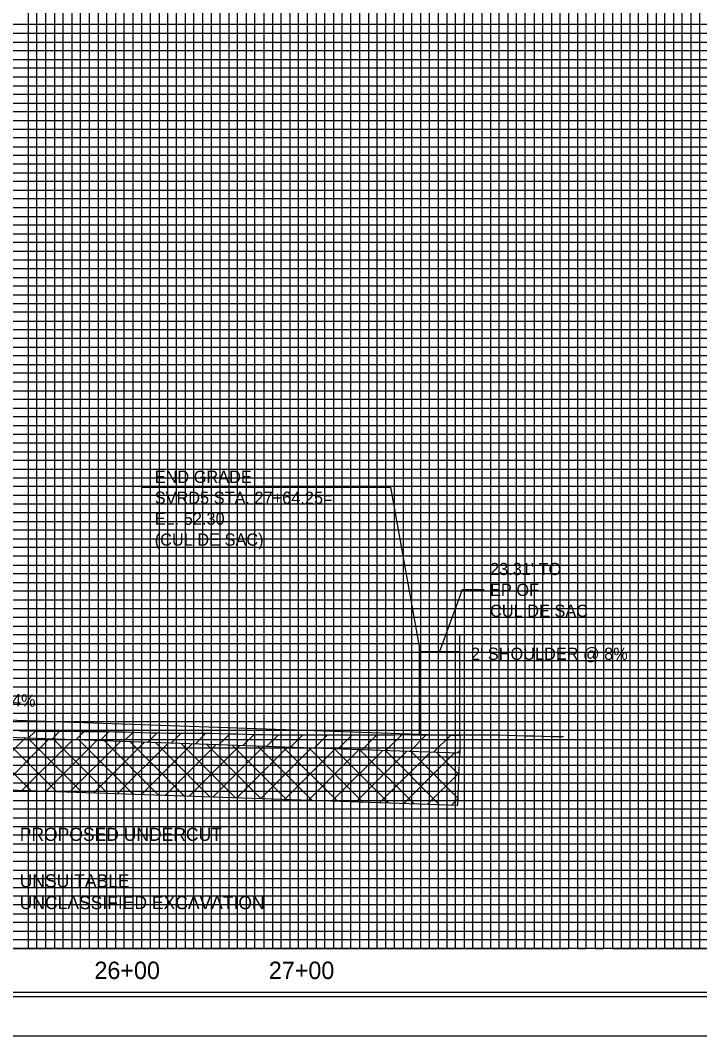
# Model space of a CAD drawing. Extents: x 2345490 to 2436403, y 465165 to 573888.
# Drawn here: x 2383276 to 2383665, y 491453 to 492035 of the extents above; entities that cross this region are included whole.
import ezdxf

# ---------------------------------------------------------------- set-up
doc = ezdxf.new("R2010")
doc.units = 0
for name, color, linetype in [('Default', 7, 'Continuous'), ('Old_Level_1', 7, 'Continuous'), ('Old_Level_18', 7, 'Continuous'), ('Old_Level_2', 7, 'Continuous'), ('Old_Level_41', 7, 'Continuous'), ('Old_Level_42', 7, 'Continuous'), ('Old_Level_43', 7, 'Continuous'), ('Old_Level_5', 7, 'Continuous'), ('Old_Level_50', 7, 'Continuous'), ('Old_Level_51', 7, 'Continuous'), ('Old_Level_62', 7, 'Continuous'), ('Old_Level_63', 7, 'Continuous'), ('Prop Vertical Profile Grade', 7, 'Continuous')]:
    doc.layers.add(name, color=color, linetype=linetype)

msp = doc.modelspace()

# ---------------------------------------------------------------- linework, layer by layer
at = {"layer": 'Default'}
msp.add_line((2383527.68499, 491625.10225), (2383527.68499, 491615.09754), dxfattribs=at)
at = {"layer": 'Old_Level_1'}
msp.add_lwpolyline([(2383275.125, 491627.81575), (2383280.125, 491627.77375), (2383285.125, 491627.7315), (2383290.125, 491627.6895), (2383295.125, 491627.6475), (2383300.125, 491627.60475), (2383305.125, 491627.56175), (2383310.125, 491627.5185), (2383315.125, 491627.4755), (2383320.125, 491627.43225), (2383325.125, 491627.389), (2383330.125, 491627.30725), (2383335.125, 491627.17775), (2383340.125, 491627.04825), (2383345.125, 491626.91875), (2383350.125, 491626.78925), (2383355.125, 491626.6595), (2383360.125, 491626.533), (2383365.125, 491626.53275), (2383370.125, 491626.5325), (2383375.125, 491626.53225), (2383380.125, 491626.532), (2383385.125, 491626.4805), (2383390.125, 491626.347), (2383395.125, 491626.2135), (2383400.125, 491626.08), (2383405.125, 491625.9465), (2383410.125, 491625.813), (2383415.125, 491625.6795), (2383420.125, 491625.546), (2383425.125, 491625.506), (2383430.125, 491625.5225), (2383435.125, 491625.53875), (2383440.125, 491625.5515), (2383445.125, 491625.5565), (2383450.125, 491625.5615), (2383455.125, 491625.5665), (2383460.125, 491625.57125), (2383465.125, 491625.57625), (2383470.125, 491625.58125), (2383475.125, 491625.58625), (2383480.125, 491625.591), (2383485.125, 491625.602), (2383490.125, 491625.63275), (2383495.125, 491625.6515), (2383500.125, 491625.63575), (2383505.125, 491625.62025), (2383510.125, 491625.60475), (2383515.125, 491625.589), (2383520.125, 491625.5735), (2383525.125, 491625.55775), (2383530.125, 491625.54225), (2383535.125, 491625.5265), (2383540.125, 491625.511), (2383545.125, 491625.49525), (2383550.125, 491625.48975), (2383555.125, 491625.34), (2383560.125, 491625.19025), (2383565.125, 491625.04025), (2383570.125, 491624.8905), (2383575.125, 491624.7405), (2383580.125, 491624.66775), (2383585.125, 491624.6015), (2383587.125, 491624.575)], dxfattribs=at)
at = {"layer": 'Old_Level_18'}
msp.add_lwpolyline([(2384590.125, 492527.95225), (2383090.125, 492527.95225), (2383090.125, 491477.95225), (2384590.125, 491477.95225)], close=True, dxfattribs=at)
at = {"layer": 'Old_Level_2'}
for p, q in [((2383344.85425, 491767.688), (2383488.04875, 491767.688)), ((2383504.375, 491676.31075), (2383488.04875, 491767.688)), ((2383528.99175, 491708.7615), (2383515.985, 491673.4475)), ((2383541.55675, 491708.7615), (2383528.99175, 491708.7615)), ((2383527.685, 491625.237), (2383527.685, 491682.5075)), ((2383504.375, 491625.95225), (2383504.375, 491676.31075)), ((2383504.375, 491673.4475), (2383527.685, 491673.4475)), ((2383504.375, 491625.95225), (2383527.685, 491625.237))]:
    msp.add_line(p, q, dxfattribs=at)
at = {"layer": 'Old_Level_41'}
msp.add_line((2384590.125, 491502.95225), (2383090.125, 491502.95225), dxfattribs=at)
for points in [[(2383090.125, 492527.95225), (2383140.125, 492527.95225), (2383140.125, 491502.95225), (2383190.125, 491502.95225), (2383190.125, 492527.95225), (2383240.125, 492527.95225), (2383240.125, 491502.95225), (2383290.125, 491502.95225), (2383290.125, 492527.95225), (2383340.125, 492527.95225), (2383340.125, 491502.95225), (2383390.125, 491502.95225), (2383390.125, 492527.95225), (2383440.125, 492527.95225), (2383440.125, 491502.95225), (2383490.125, 491502.95225), (2383490.125, 492527.95225), (2383540.125, 492527.95225), (2383540.125, 491502.95225), (2383590.125, 491502.95225), (2383590.125, 492527.95225), (2383640.125, 492527.95225), (2383640.125, 491502.95225), (2383690.125, 491502.95225)], [(2383165.125, 491502.95225), (2383165.125, 492527.95225), (2383215.125, 492527.95225), (2383215.125, 491502.95225), (2383265.125, 491502.95225), (2383265.125, 492527.95225), (2383315.125, 492527.95225), (2383315.125, 491502.95225), (2383365.125, 491502.95225), (2383365.125, 492527.95225), (2383415.125, 492527.95225), (2383415.125, 491502.95225), (2383465.125, 491502.95225), (2383465.125, 492527.95225), (2383515.125, 492527.95225), (2383515.125, 491502.95225), (2383565.125, 491502.95225), (2383565.125, 492527.95225), (2383615.125, 492527.95225), (2383615.125, 491502.95225), (2383665.125, 491502.95225), (2383665.125, 492527.95225), (2383715.125, 492527.95225)], [(2384590.125, 492027.95225), (2383090.125, 492027.95225), (2383090.125, 491977.95225), (2384590.125, 491977.95225)], [(2384590.125, 491927.95225), (2383090.125, 491927.95225), (2383090.125, 491877.95225), (2384590.125, 491877.95225)], [(2384590.125, 491852.95225), (2383090.125, 491852.95225), (2383090.125, 491902.95225), (2384590.125, 491902.95225)], [(2384590.125, 491827.95225), (2383090.125, 491827.95225), (2383090.125, 491777.95225), (2384590.125, 491777.95225)], [(2384590.125, 491752.95225), (2383090.125, 491752.95225), (2383090.125, 491802.95225), (2384590.125, 491802.95225)], [(2384590.125, 491727.95225), (2383090.125, 491727.95225), (2383090.125, 491677.95225), (2384590.125, 491677.95225)], [(2384590.125, 491627.95225), (2383090.125, 491627.95225), (2383090.125, 491577.95225), (2384590.125, 491577.95225)], [(2384590.125, 491552.95225), (2383090.125, 491552.95225), (2383090.125, 491602.95225), (2384590.125, 491602.95225)], [(2384590.125, 491527.95225), (2383090.125, 491527.95225)]]:
    msp.add_lwpolyline(points, dxfattribs=at)
at = {"layer": 'Old_Level_42'}
for points in [[(2384590.125, 491952.95225), (2383090.125, 491952.95225), (2383090.125, 492002.95225), (2384590.125, 492002.95225)], [(2384590.125, 491652.95225), (2383090.125, 491652.95225), (2383090.125, 491702.95225), (2384590.125, 491702.95225)]]:
    msp.add_lwpolyline(points, dxfattribs=at)
at = {"layer": 'Old_Level_43'}
for points in [[(2383280.125, 492527.95225), (2383280.125, 491502.95225), (2383285.125, 491502.95225), (2383285.125, 492527.95225)], [(2383295.125, 492527.95225), (2383295.125, 491502.95225), (2383300.125, 491502.95225), (2383300.125, 492527.95225)], [(2383305.125, 491502.95225), (2383310.125, 491502.95225), (2383310.125, 492527.95225)], [(2383305.125, 492527.95225), (2383305.125, 491502.95225)], [(2383320.125, 492527.95225), (2383320.125, 491502.95225), (2383325.125, 491502.95225), (2383325.125, 492527.95225)], [(2383330.125, 492527.95225), (2383330.125, 491502.95225), (2383335.125, 491502.95225), (2383335.125, 492527.95225)], [(2383345.125, 492527.95225), (2383345.125, 491502.95225), (2383350.125, 491502.95225), (2383350.125, 492527.95225)], [(2383355.125, 492527.95225), (2383355.125, 491502.95225), (2383360.125, 491502.95225), (2383360.125, 492527.95225)], [(2383370.125, 492527.95225), (2383370.125, 491502.95225), (2383375.125, 491502.95225), (2383375.125, 492527.95225)], [(2383380.125, 492527.95225), (2383380.125, 491502.95225), (2383385.125, 491502.95225), (2383385.125, 492527.95225)], [(2383395.125, 492527.95225), (2383395.125, 491502.95225), (2383400.125, 491502.95225), (2383400.125, 492527.95225)], [(2383405.125, 492527.95225), (2383405.125, 491502.95225), (2383410.125, 491502.95225), (2383410.125, 492527.95225)], [(2383420.125, 492527.95225), (2383420.125, 491502.95225), (2383425.125, 491502.95225), (2383425.125, 492527.95225)], [(2383430.125, 492527.95225), (2383430.125, 491502.95225), (2383435.125, 491502.95225), (2383435.125, 492527.95225)], [(2383445.125, 492527.95225), (2383445.125, 491502.95225), (2383450.125, 491502.95225), (2383450.125, 492527.95225)], [(2383455.125, 492527.95225), (2383455.125, 491502.95225), (2383460.125, 491502.95225), (2383460.125, 492527.95225)], [(2383470.125, 492527.95225), (2383470.125, 491502.95225), (2383485.125, 491502.95225), (2383485.125, 492527.95225)], [(2383475.125, 492527.95225), (2383475.125, 491502.95225), (2383480.125, 491502.95225), (2383480.125, 492527.95225)], [(2383475.125, 492527.35225), (2383475.125, 491502.95225), (2383480.125, 491502.95225), (2383480.125, 492527.35225)], [(2383495.125, 492527.95225), (2383495.125, 491502.95225), (2383500.125, 491502.95225), (2383500.125, 492527.95225)], [(2383505.125, 492527.95225), (2383505.125, 491502.95225), (2383510.125, 491502.95225), (2383510.125, 492527.95225)], [(2383520.125, 492527.95225), (2383520.125, 491502.95225), (2383525.125, 491502.95225), (2383525.125, 492527.95225)], [(2383530.125, 492527.95225), (2383530.125, 491502.95225), (2383535.125, 491502.95225), (2383535.125, 492527.95225)], [(2383545.125, 492527.95225), (2383545.125, 491502.95225), (2383550.125, 491502.95225), (2383550.125, 492527.95225)], [(2383555.125, 492527.95225), (2383555.125, 491502.95225), (2383560.125, 491502.95225), (2383560.125, 492527.95225)], [(2383570.125, 492527.95225), (2383570.125, 491502.95225), (2383575.125, 491502.95225), (2383575.125, 492527.95225)], [(2383580.125, 492527.95225), (2383580.125, 491502.95225), (2383585.125, 491502.95225), (2383585.125, 492527.95225)], [(2383595.125, 492527.95225), (2383595.125, 491502.95225), (2383600.125, 491502.95225), (2383600.125, 492527.95225)], [(2383605.125, 492527.95225), (2383605.125, 491502.95225), (2383610.125, 491502.95225), (2383610.125, 492527.95225)], [(2383620.125, 492527.95225), (2383620.125, 491502.95225)], [(2383625.125, 492527.95225), (2383625.125, 491502.95225), (2383630.125, 491502.95225), (2383630.125, 492527.95225), (2383635.125, 492527.95225), (2383635.125, 491502.95225), (2383645.125, 491502.95225), (2383645.125, 492527.95225), (2383650.125, 492527.95225), (2383650.125, 491502.95225), (2383655.125, 491502.95225), (2383655.125, 492527.95225), (2383660.125, 492527.95225), (2383660.125, 491502.95225)], [(2384540.125, 492032.95225), (2383140.125, 492032.95225), (2383140.125, 492022.95225), (2384540.125, 492022.95225)], [(2384540.125, 492017.95225), (2383140.125, 492017.95225), (2383140.125, 492012.95225), (2384540.125, 492012.95225)], [(2384540.125, 492007.95225), (2383140.125, 492007.95225)], [(2383140.125, 491997.95225), (2384540.125, 491997.95225)], [(2384540.125, 491992.95225), (2383140.125, 491992.95225), (2383140.125, 491987.95225), (2384540.125, 491987.95225)], [(2384540.125, 491982.95225), (2383140.125, 491982.95225), (2383140.125, 491972.95225), (2384540.125, 491972.95225)], [(2384540.125, 491967.95225), (2383140.125, 491967.95225), (2383140.125, 491962.95225), (2384540.125, 491962.95225)], [(2384540.125, 491957.95225), (2383140.125, 491957.95225), (2383140.125, 491947.95225), (2384540.125, 491947.95225)], [(2384540.125, 491942.95225), (2383140.125, 491942.95225), (2383140.125, 491937.95225), (2384540.125, 491937.95225)], [(2384540.125, 491932.95225), (2383140.125, 491932.95225), (2383140.125, 491922.95225), (2384540.125, 491922.95225)], [(2384540.125, 491917.95225), (2383140.125, 491917.95225), (2383140.125, 491912.95225), (2384540.125, 491912.95225)], [(2384540.125, 491907.95225), (2383140.125, 491907.95225), (2383140.125, 491897.95225), (2384540.125, 491897.95225)], [(2384540.125, 491892.95225), (2383140.125, 491892.95225), (2383140.125, 491887.95225), (2384540.125, 491887.95225)], [(2384540.125, 491882.95225), (2383140.125, 491882.95225), (2383140.125, 491872.95225), (2384540.125, 491872.95225)], [(2384540.125, 491867.95225), (2383140.125, 491867.95225), (2383140.125, 491862.95225), (2384540.125, 491862.95225)], [(2384540.125, 491857.95225), (2383140.125, 491857.95225), (2383140.125, 491847.95225), (2384540.125, 491847.95225)], [(2384540.125, 491842.95225), (2383140.125, 491842.95225), (2383140.125, 491837.95225), (2384540.125, 491837.95225)], [(2384540.125, 491832.95225), (2383140.125, 491832.95225), (2383140.125, 491822.95225), (2384540.125, 491822.95225)], [(2384540.125, 491817.95225), (2383140.125, 491817.95225), (2383140.125, 491812.95225), (2384540.125, 491812.95225)], [(2384540.125, 491807.95225), (2383140.125, 491807.95225), (2383140.125, 491797.95225), (2384540.125, 491797.95225)], [(2384540.125, 491792.95225), (2383140.125, 491792.95225), (2383140.125, 491787.95225), (2384540.125, 491787.95225)], [(2384540.125, 491782.95225), (2383140.125, 491782.95225), (2383140.125, 491772.95225), (2384540.125, 491772.95225)], [(2384540.125, 491767.95225), (2383140.125, 491767.95225), (2383140.125, 491762.95225), (2384540.125, 491762.95225)], [(2384540.125, 491757.95225), (2383140.125, 491757.95225), (2383140.125, 491747.95225), (2384540.125, 491747.95225)], [(2384540.125, 491742.95225), (2383140.125, 491742.95225), (2383140.125, 491737.95225), (2384540.125, 491737.95225)], [(2384540.125, 491732.95225), (2383140.125, 491732.95225), (2383140.125, 491722.95225), (2384540.125, 491722.95225)], [(2384540.125, 491717.95225), (2383140.125, 491717.95225), (2383140.125, 491712.95225), (2384540.125, 491712.95225)], [(2384540.125, 491707.95225), (2383140.125, 491707.95225)], [(2383140.125, 491697.95225), (2384540.125, 491697.95225)], [(2384540.125, 491692.95225), (2383140.125, 491692.95225), (2383140.125, 491687.95225), (2384540.125, 491687.95225)], [(2384540.125, 491682.95225), (2383140.125, 491682.95225)], [(2383140.125, 491672.95225), (2384540.125, 491672.95225)], [(2384540.125, 491667.95225), (2383140.125, 491667.95225), (2383140.125, 491662.95225), (2384540.125, 491662.95225)], [(2384540.125, 491657.95225), (2383140.125, 491657.95225), (2383140.125, 491647.95225), (2384540.125, 491647.95225)], [(2384540.125, 491642.95225), (2383140.125, 491642.95225), (2383140.125, 491637.95225), (2384540.125, 491637.95225)], [(2384540.125, 491632.95225), (2383140.125, 491632.95225), (2383140.125, 491622.95225), (2384540.125, 491622.95225)], [(2384540.125, 491617.95225), (2383140.125, 491617.95225), (2383140.125, 491612.95225), (2384540.125, 491612.95225)], [(2384540.125, 491607.95225), (2383140.125, 491607.95225), (2383140.125, 491597.95225), (2384540.125, 491597.95225)], [(2384540.125, 491592.95225), (2383140.125, 491592.95225), (2383140.125, 491587.95225), (2384540.125, 491587.95225)], [(2384540.125, 491582.95225), (2383140.125, 491582.95225), (2383140.125, 491572.95225), (2384540.125, 491572.95225)], [(2384540.125, 491567.95225), (2383140.125, 491567.95225), (2383140.125, 491562.95225), (2384540.125, 491562.95225)], [(2384540.125, 491557.95225), (2383140.125, 491557.95225), (2383140.125, 491547.95225), (2384540.125, 491547.95225)], [(2384540.125, 491542.95225), (2383140.125, 491542.95225), (2383140.125, 491537.95225), (2384540.125, 491537.95225)], [(2384540.125, 491532.95225), (2383140.125, 491532.95225), (2383140.125, 491522.95225), (2384540.125, 491522.95225)], [(2384540.125, 491517.95225), (2383140.125, 491517.95225), (2383140.125, 491512.95225), (2384540.125, 491512.95225)], [(2384540.125, 491507.95225), (2383140.125, 491507.95225)]]:
    msp.add_lwpolyline(points, dxfattribs=at)
at = {"layer": 'Old_Level_5'}
for p, q in [((2383250.56825, 491624.62775), (2383281.64915, 491593.54685)), ((2383280.1495, 491623.6085), (2383284.05659, 491627.51559)), ((2383293.81688, 491623.13374), (2383298.068, 491627.38487)), ((2383307.48425, 491622.65899), (2383312.07941, 491627.25414)), ((2383321.15163, 491622.18423), (2383326.09082, 491627.12341)), ((2383334.81901, 491621.70947), (2383340.00198, 491626.89244)), ((2383348.48639, 491621.23471), (2383353.78831, 491626.53664)), ((2383362.15377, 491620.75996), (2383367.62782, 491626.23401)), ((2383375.82114, 491620.2852), (2383381.61159, 491626.07564)), ((2383389.48852, 491619.81044), (2383395.59536, 491625.91728)), ((2383403.1559, 491619.33568), (2383409.58453, 491625.76432)), ((2383416.82328, 491618.86092), (2383423.58152, 491625.61917)), ((2383430.49066, 491618.38617), (2383437.57851, 491625.47402)), ((2383444.15803, 491617.91141), (2383451.57549, 491625.32887)), ((2383457.82541, 491617.43665), (2383465.71763, 491625.32887)), ((2383471.49279, 491616.96189), (2383479.88811, 491625.35721)), ((2383485.16017, 491616.48714), (2383494.05859, 491625.38556)), ((2383498.82754, 491616.01238), (2383508.1812, 491625.36604)), ((2383512.51351, 491615.5562), (2383522.1965, 491625.2392)), ((2383249.35625, 491594.65832), (2383278.3603, 491623.66236)), ((2383263.02784, 491594.18776), (2383292.02768, 491623.1876)), ((2383265.21931, 491624.11883), (2383296.29538, 491593.04276)), ((2383276.69942, 491593.71721), (2383305.69506, 491622.71285)), ((2383279.87037, 491623.6099), (2383310.94161, 491592.53866)), ((2383290.37101, 491593.24666), (2383319.36244, 491622.2381)), ((2383294.52143, 491623.10098), (2383325.58784, 491592.03456)), ((2383304.04259, 491592.77611), (2383333.02982, 491621.76334)), ((2383309.17248, 491622.59206), (2383340.23408, 491591.53047)), ((2383317.71418, 491592.30556), (2383346.69721, 491621.28859)), ((2383323.82354, 491622.08313), (2383354.88031, 491591.02637)), ((2383331.38576, 491591.83501), (2383360.36459, 491620.81384)), ((2383338.4746, 491621.57421), (2383369.52654, 491590.52227)), ((2383345.05734, 491591.36446), (2383374.03197, 491620.33908)), ((2383353.12566, 491621.06529), (2383384.17277, 491590.01818)), ((2383358.72893, 491590.89391), (2383387.69935, 491619.86433)), ((2383367.77672, 491620.55637), (2383398.81901, 491589.51408)), ((2383372.40051, 491590.42336), (2383401.36673, 491619.38957)), ((2383382.42778, 491620.04744), (2383413.46524, 491589.00998)), ((2383386.0721, 491589.9528), (2383415.03411, 491618.91482)), ((2383397.07884, 491619.53852), (2383428.11147, 491588.50589)), ((2383399.74368, 491589.48225), (2383428.7015, 491618.44007)), ((2383411.72989, 491619.0296), (2383442.7577, 491588.00179)), ((2383426.38095, 491618.52067), (2383457.40393, 491587.49769)), ((2383413.41527, 491589.0117), (2383442.36888, 491617.96531)), ((2383427.08685, 491588.54115), (2383456.03626, 491617.49056)), ((2383440.75844, 491588.0706), (2383469.70364, 491617.01581)), ((2383441.03201, 491618.01175), (2383472.05017, 491586.9936)), ((2383454.43002, 491587.60005), (2383483.37102, 491616.54105)), ((2383455.68307, 491617.50283), (2383486.6964, 491586.4895)), ((2383468.10161, 491587.1295), (2383497.03841, 491616.0663)), ((2383470.33413, 491616.99391), (2383501.34263, 491585.9854)), ((2383481.77319, 491586.65895), (2383510.73188, 491615.61764)), ((2383484.98519, 491616.48498), (2383515.98886, 491585.48131)), ((2383495.44477, 491586.1884), (2383524.453, 491615.19662)), ((2383499.63624, 491615.97606), (2383526.61675, 491588.99556)), ((2383514.24459, 491615.50986), (2383527.17276, 491602.58168)), ((2383526.23457, 491615.13513), (2383527.68499, 491616.58555)), ((2383509.11636, 491585.71784), (2383527.22365, 491603.82514)), ((2383522.78794, 491585.24729), (2383526.62018, 491589.07953))]:
    msp.add_line(p, q, dxfattribs=at)
msp.add_lwpolyline([(2382934.83795, 491597.73858), (2383032.62499, 491604.97631), (2383047.62499, 491604.97631), (2383183.48336, 491596.60422), (2383228.76328, 491595.36718), (2383526.4582, 491585.12107), (2383527.68499, 491615.09754), (2383504.06829, 491615.8222), (2383229.77783, 491625.35003), (2383144.70493, 491627.10041), (2383030.41861, 491625.82181), (2382939.67787, 491624.39126), (2382935.12499, 491599.31925)], dxfattribs=at)
at = {"layer": 'Old_Level_50'}
msp.add_lwpolyline([(2384602.625, 492530.50225), (2382936.125, 492530.50225), (2382936.125, 491475.40225), (2384602.625, 491475.40225)], close=True, dxfattribs=at)
at = {"layer": 'Old_Level_51'}
msp.add_lwpolyline([(2384607.125, 492552.95225), (2382923.125, 492552.95225), (2382923.125, 491452.95225), (2384607.125, 491452.95225)], close=True, dxfattribs=at)
at = {"layer": 'Old_Level_63'}
msp.add_line((2381740.125, 491502.95225), (2383587.28325, 491502.95225), dxfattribs=at)
at = {"layer": 'Prop Vertical Profile Grade'}
msp.add_line((2383230.125, 491635.47869), (2383504.375, 491625.9523), dxfattribs=at)

# ---------------------------------------------------------------- texts
at = {"layer": 'Old_Level_2'}
for s, height, p in [('END GRADE', 7.000001, (2383352.641, 491770.05975)), ('SVRD5 STA. 27+64.25=', 7.0000005, (2383352.641, 491758.05975)), ('EL. 52.30', 7.000001, (2383352.641, 491746.05975)), ('(CUL DE SAC)', 7.0000005, (2383352.641, 491734.05975)), ("23.31' TO ", 7.000001, (2383544.91675, 491717.203)), ('EP OF ', 7.000001, (2383544.91675, 491705.203)), ('CUL DE SAC', 7.000001, (2383544.91675, 491693.203)), ("2' SHOULDER @ 8% ", 7.0000005, (2383534.0406, 491668.56306))]:
    msp.add_text(s, height=height, dxfattribs=at).set_placement(p)
msp.add_text('(-)0.3474%', height=7, rotation=358.01056573, dxfattribs=at).set_placement((2383237.91716, 491643.19607))
at = {"layer": 'Old_Level_5'}
for s, p in [('PROPOSED UNDERCUT', (2383275.23474, 491564.71674)), ('UNSUITABLE', (2383275.23474, 491538.05279)), ('UNCLASSIFIED EXCAVATION', (2383275.23474, 491525.55279))]:
    msp.add_text(s, height=7.5, dxfattribs=at).set_placement(p)
at = {"layer": 'Old_Level_62'}
for s, p in [('26+00', (2383318.057, 491485.45225)), ('27+00', (2383418.057, 491485.45225))]:
    msp.add_text(s, height=10.000001, dxfattribs=at).set_placement(p)

doc.saveas('drawing.dxf')
